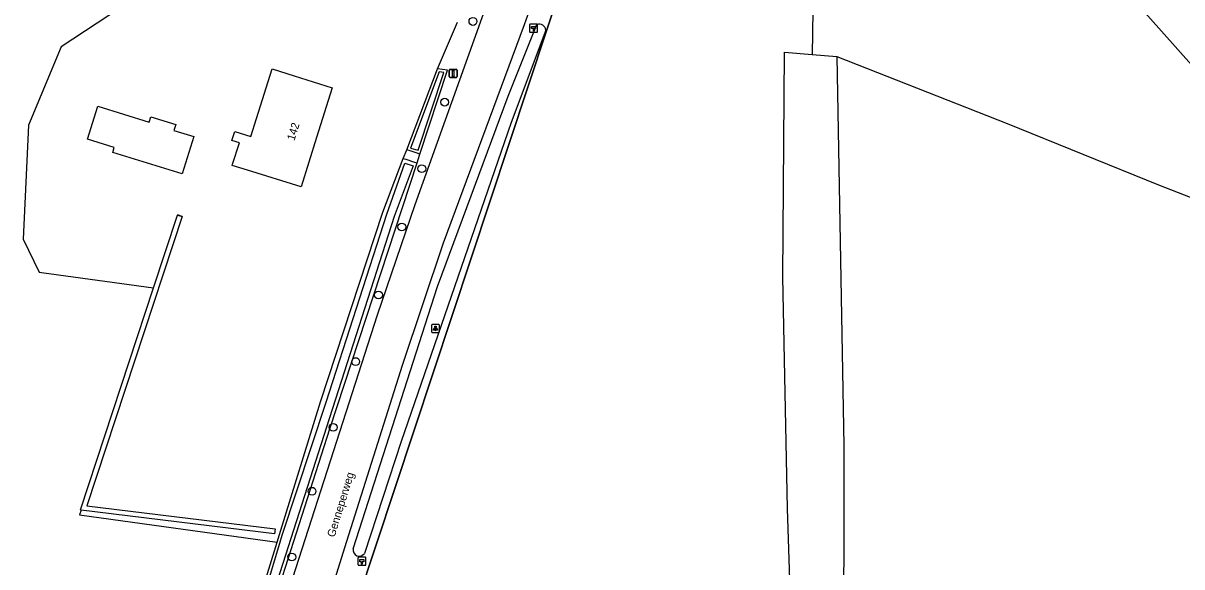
# Model space of a CAD drawing. Extents: x 160203 to 161526, y 379529 to 381797.
# Drawn here: x 160911.8 to 161056.6, y 381132.5 to 381200.5 of the extents above; entities that cross this region are included whole.
import ezdxf

# ---------------------------------------------------------------- set-up
doc = ezdxf.new("R2010")
doc.units = 0
for name, color, linetype in [('IMGEO_Berm_groen', 7, 'Continuous'), ('IMGEO_Boom', 7, 'Continuous'), ('IMGEO_Bouwland', 7, 'Continuous'), ('IMGEO_Erf', 7, 'Continuous'), ('IMGEO_Grasland_agrarisch', 7, 'Continuous'), ('IMGEO_Groenvoorziening', 7, 'Continuous'), ('IMGEO_Haag', 7, 'Continuous'), ('IMGEO_Hectometerpaal', 7, 'Continuous'), ('IMGEO_Hek', 7, 'Continuous'), ('IMGEO_Houtwal', 7, 'Continuous'), ('IMGEO_Lichtpunt', 7, 'Continuous'), ('IMGEO_Loofbos', 7, 'Continuous'), ('IMGEO_Openbare_ruimte_label', 7, 'Continuous'), ('IMGEO_Pand', 7, 'Continuous'), ('IMGEO_Pand_nummerreeks', 7, 'Continuous'), ('IMGEO_Rijbaan_lokaal_gesloten', 7, 'Continuous'), ('IMGEO_Verkeersbordpaal', 7, 'Continuous'), ('IMGEO_Waterloop', 7, 'Continuous')]:
    doc.layers.add(name, color=color, linetype=linetype)

msp = doc.modelspace()

# ---------------------------------------------------------------- linework, layer by layer
at = {"layer": 'IMGEO_Berm_groen'}
for points in [[(160963.6, 381194.73), (160966.09, 381200.58)], [(160961.4, 381184.09), (160964.85, 381194.6), (160963.6, 381194.73)], [(160961.04, 381182.98), (160961.4, 381184.09)], [(160939.06, 381120.95), (160940.77, 381120.43), (160950.14, 381149.71), (160961.04, 381182.98)]]:
    msp.add_lwpolyline(points, dxfattribs=at)
at = {"layer": 'IMGEO_Boom'}
for centre in [(160968.03, 381200.68), (160964.5, 381190.58), (160961.64, 381182.26), (160959.14, 381174.97), (160956.23, 381166.46), (160953.38, 381158.13), (160950.56, 381149.9), (160947.92, 381141.91), (160945.39, 381133.68)]:
    msp.add_circle(centre, 0.489, dxfattribs=at)
at = {"layer": 'IMGEO_Bouwland'}
for points in [[(161010.97, 381081.3), (161010.95, 381074.65), (161003.55, 381076.23), (161000, 381077.09), (160995.21, 381078.26), (160994.38, 381077.68), (160975.97, 381079.3), (160943.93, 381083.76), (160939.3, 381085.02), (160993.95, 381250), (160994.1, 381250.44), (160995.16, 381250.16), (160995.77, 381250), (161000, 381248.89), (161006.71, 381247.12)], [(161010.51, 381202), (161010.41, 381196.55)], [(161013.52, 381196.31), (161034.78, 381187.91), (161053.72, 381180.26), (161083.68, 381168.57)]]:
    msp.add_lwpolyline(points, dxfattribs=at)
at = {"layer": 'IMGEO_Erf'}
for points in [[(160959.75, 381184.63), (160963.6, 381194.73)], [(160943.56, 381135.52), (160943.86, 381136.52), (160948.98, 381153.08), (160956.78, 381176.82), (160959.33, 381183.53)]]:
    msp.add_lwpolyline(points, dxfattribs=at)
at = {"layer": 'IMGEO_Grasland_agrarisch'}
for points in [[(160965.13, 381205.95), (160950.45, 381206.63), (160940.17, 381205.98), (160925.58, 381203.46), (160916.58, 381197.51), (160912.48, 381187.72), (160911.82, 381173.43), (160913.8, 381169.33), (160914.13, 381169.27), (160928.12, 381167.36)], [(160919.06, 381139.56), (160918.86, 381138.97), (160943.56, 381135.52)], [(160939.06, 381120.95), (160943.56, 381135.52)]]:
    msp.add_lwpolyline(points, dxfattribs=at)
at = {"layer": 'IMGEO_Groenvoorziening'}
for points in [[(160959.33, 381183.53), (160959.75, 381184.63)], [(160961.4, 381184.09), (160961.08, 381184.2), (160960.08, 381184.52), (160959.75, 381184.63)], [(160959.33, 381183.53), (160959.66, 381183.43), (160960.71, 381183.08), (160961.04, 381182.98)], [(160931.1, 381176.45), (160931.68, 381176.29)]]:
    msp.add_lwpolyline(points, dxfattribs=at)
at = {"layer": 'IMGEO_Haag'}
for points in [[(160931.68, 381176.29), (160919.77, 381140.08), (160943.31, 381137.19), (160943.24, 381136.59), (160919.06, 381139.56)], [(160928.12, 381167.36), (160931.1, 381176.45)], [(160931.68, 381176.29), (160931.12, 381176.48), (160931.1, 381176.45)], [(160919.06, 381139.56), (160918.98, 381139.57), (160928.12, 381167.36)]]:
    msp.add_lwpolyline(points, dxfattribs=at)
at = {"layer": 'IMGEO_Hectometerpaal'}
for p, q in [((160975.12, 381200.25), (160975.12, 381199.41)), ((160975.12, 381200.25), (160975.12, 381199.41)), ((160976.03, 381200.33), (160975.19, 381200.33)), ((160976.03, 381200.33), (160975.19, 381200.33)), ((160975.2, 381199.33), (160976.04, 381199.33)), ((160975.2, 381199.33), (160976.04, 381199.33)), ((160976.11, 381199.42), (160976.11, 381200.26)), ((160976.11, 381199.42), (160976.11, 381200.26)), ((160953.66, 381133.56), (160953.66, 381132.72)), ((160953.66, 381133.56), (160953.66, 381132.72)), ((160954.57, 381133.65), (160953.73, 381133.65)), ((160954.57, 381133.65), (160953.73, 381133.65)), ((160953.74, 381132.65), (160954.58, 381132.65)), ((160953.74, 381132.65), (160954.58, 381132.65)), ((160954.66, 381132.73), (160954.66, 381133.57)), ((160954.66, 381132.73), (160954.66, 381133.57))]:
    msp.add_line(p, q, dxfattribs=at)
for points in [[(160975.64, 381199.48), (160975.58, 381199.48), (160975.58, 381199.78), (160975.36, 381199.78), (160975.36, 381200.05), (160975.86, 381200.05), (160975.86, 381199.78), (160975.64, 381199.78), (160975.64, 381199.48)], [(160954.18, 381132.79), (160954.12, 381132.79), (160954.12, 381133.1), (160953.9, 381133.1), (160953.9, 381133.37), (160954.4, 381133.37), (160954.4, 381133.1), (160954.18, 381133.1), (160954.18, 381132.79)]]:
    msp.add_lwpolyline(points, dxfattribs=at)
for centre, start, end in [((160975.19, 381200.25), 92.4484, 184.2845), ((160975.19, 381200.25), 92.4484, 184.2845), ((160975.19, 381199.41), 182.4484, 274.2845), ((160975.19, 381199.41), 182.4484, 274.2845), ((160976.04, 381200.25), 2.4484, 94.2845), ((160976.04, 381200.25), 2.4484, 94.2845), ((160976.04, 381199.41), 272.4484, 4.2845), ((160976.04, 381199.41), 272.4484, 4.2845), ((160953.74, 381133.57), 92.4484, 184.2845), ((160953.74, 381133.57), 92.4484, 184.2845), ((160953.74, 381132.73), 182.4484, 274.2845), ((160953.74, 381132.73), 182.4484, 274.2845), ((160954.58, 381133.57), 2.4484, 94.2845), ((160954.58, 381133.57), 2.4484, 94.2845), ((160954.58, 381132.73), 272.4484, 4.2845), ((160954.58, 381132.73), 272.4484, 4.2845)]:
    msp.add_arc(centre, 0.0779, start, end, dxfattribs=at)
at = {"layer": 'IMGEO_Hek'}
msp.add_lwpolyline([(160995.16, 381250.16), (160994.1, 381250.44), (160993.95, 381250), (160939.3, 381085.02), (160943.93, 381083.76), (160975.97, 381079.3), (160994.38, 381077.68), (160995.21, 381078.26), (161000, 381077.09), (161003.55, 381076.23), (161010.95, 381074.65)], dxfattribs=at)
at = {"layer": 'IMGEO_Houtwal'}
for points in [[(161010.97, 381081.3), (161009.28, 381081.26), (161007.34, 381139.77), (161006.78, 381168.69), (161006.96, 381196.82), (161010.41, 381196.55)], [(161010.41, 381196.55), (161013.52, 381196.31)], [(161013.52, 381196.31), (161014.4, 381147.63), (161014.3, 381086.66), (161013.49, 381081.36)]]:
    msp.add_lwpolyline(points, dxfattribs=at)
at = {"layer": 'IMGEO_Lichtpunt'}
for p, q in [((160962.85, 381162.67), (160962.85, 381161.87)), ((160962.85, 381162.67), (160962.85, 381161.87)), ((160963.75, 381162.77), (160962.94, 381162.77)), ((160963.75, 381162.77), (160962.94, 381162.77)), ((160962.94, 381161.77), (160963.75, 381161.77)), ((160962.94, 381161.77), (160963.75, 381161.77)), ((160963.85, 381161.87), (160963.85, 381162.67)), ((160963.85, 381161.87), (160963.85, 381162.67))]:
    msp.add_line(p, q, dxfattribs=at)
for points in [[(160963.22, 381162.34), (160963.26, 381162.31), (160963.08, 381162.05), (160963.04, 381162.08), (160963.22, 381162.34)], [(160963.33, 381162.29), (160963.37, 381162.29), (160963.37, 381161.97), (160963.33, 381161.97), (160963.33, 381162.29)], [(160963.44, 381162.31), (160963.47, 381162.34), (160963.66, 381162.07), (160963.62, 381162.05), (160963.44, 381162.31)]]:
    msp.add_lwpolyline(points, dxfattribs=at)
msp.add_circle((160963.35, 381162.47), 0.0994, dxfattribs=at)
for centre, start, end in [((160962.94, 381162.67), 90, 180), ((160962.94, 381162.67), 90, 180), ((160962.94, 381161.87), 180, 270), ((160962.94, 381161.87), 180, 270), ((160963.75, 381162.67), 0, 90), ((160963.75, 381162.67), 0, 90), ((160963.75, 381161.87), 270, 0), ((160963.75, 381161.87), 270, 360)]:
    msp.add_arc(centre, 0.0946, start, end, dxfattribs=at)
at = {"layer": 'IMGEO_Loofbos'}
msp.add_lwpolyline([(161082.58, 381175.75), (161077.67, 381178.3), (161070.58, 381182.79), (161061.58, 381191.03), (161050.68, 381203.28), (161037.87, 381219.57), (161034.13, 381223.39), (161013.62, 381201.68), (161010.51, 381202)], dxfattribs=at)
at = {"layer": 'IMGEO_Pand'}
for points in [[(160939.84, 381182.08), (160937.95, 381182.67), (160938, 381182.82), (160938.84, 381185.5), (160937.91, 381185.79), (160938.26, 381186.9), (160940.27, 381186.27), (160940.98, 381188.54), (160942.93, 381194.74), (160945.68, 381193.87), (160950.45, 381192.38), (160948.5, 381186.17), (160946.55, 381179.97), (160939.84, 381182.08)], [(160931.68, 381181.6), (160923.03, 381184.29), (160923.2, 381184.91), (160919.87, 381185.95), (160921.16, 381190.08), (160927.57, 381188.08), (160927.78, 381188.74), (160930.88, 381187.77), (160930.66, 381187.05), (160933.14, 381186.28), (160931.68, 381181.6)]]:
    msp.add_lwpolyline(points, dxfattribs=at)
at = {"layer": 'IMGEO_Rijbaan_lokaal_gesloten'}
for points in [[(160986.23, 381250.71), (160986.06, 381250), (160984.88, 381245.18), (160960.77, 381177.72), (160956.05, 381163.95), (160940.76, 381116.4)], [(160915.33, 381026.22), (160921.46, 381041.16), (160927.74, 381060.12), (160928.46, 381062.22), (160929.84, 381066.2), (160933.95, 381078.05), (160934.49, 381079.74), (160949.77, 381127.68), (160952.02, 381134.89), (160959.23, 381157.7), (160964.36, 381173), (160974.47, 381200.28), (160974.68, 381200.87), (160988.22, 381238.39), (160991.59, 381248.5)]]:
    msp.add_lwpolyline(points, dxfattribs=at)
at = {"layer": 'IMGEO_Verkeersbordpaal'}
for p, q in [((160965.07, 381193.78), (160965.07, 381194.58)), ((160965.07, 381194.58), (160965.07, 381193.78)), ((160965.17, 381194.68), (160965.96, 381194.68)), ((160965.96, 381194.68), (160965.17, 381194.68)), ((160965.96, 381193.68), (160965.17, 381193.68)), ((160965.17, 381193.68), (160965.96, 381193.68)), ((160966.06, 381194.58), (160966.06, 381193.78)), ((160966.06, 381193.78), (160966.06, 381194.58))]:
    msp.add_line(p, q, dxfattribs=at)
msp.add_lwpolyline([(160965.49, 381194.55), (160965.64, 381194.55), (160965.64, 381193.8), (160965.49, 381193.8), (160965.49, 381194.55)], dxfattribs=at)
for centre, start, end in [((160965.17, 381194.58), 90, 180), ((160965.17, 381194.58), 90, 180), ((160965.17, 381193.78), 180, 270), ((160965.17, 381193.78), 180, 270), ((160965.96, 381194.58), 0, 90), ((160965.96, 381194.58), 360, 90), ((160965.96, 381193.78), 270, 0), ((160965.96, 381193.78), 270, 0)]:
    msp.add_arc(centre, 0.1, start, end, dxfattribs=at)
at = {"layer": 'IMGEO_Waterloop'}
for points in [[(160953.05, 381134.71), (160963.59, 381167.51), (160972.42, 381191.32), (160976.03, 381200.31)], [(160977.15, 381199.6), (160972.82, 381188.05), (160959.08, 381148.14)], [(160960.23, 381184.83), (160961.2, 381184.56), (160964.39, 381194.3), (160963.82, 381194.36), (160960.23, 381184.83)], [(160939.64, 381121.3), (160943.88, 381135.42), (160944.19, 381136.41), (160949.68, 381153.06), (160957.28, 381176.57), (160959.5, 381182.97), (160960.55, 381182.63), (160958.17, 381176.29), (160949.71, 381149.93), (160940.49, 381121.04), (160939.64, 381121.3)], [(160959.08, 381148.14), (160954.48, 381134.13)]]:
    msp.add_lwpolyline(points, dxfattribs=at)
for centre, radius, start, end in [((160976.3, 381199.5), 0.852, 6.5141, 108.5302), ((160953.83, 381134.58), 0.788, 170.441, 324.9041)]:
    msp.add_arc(centre, radius, start, end, dxfattribs=at)

# ---------------------------------------------------------------- texts
at = {"layer": 'IMGEO_Openbare_ruimte_label'}
msp.add_text('Genneperweg', height=1, rotation=72.9605, dxfattribs=at).set_placement((160950.73, 381136.08))
at = {"layer": 'IMGEO_Pand_nummerreeks'}
msp.add_text('142', height=1, rotation=72.5594, dxfattribs=at).set_placement((160945.71, 381185.7))

doc.saveas('drawing.dxf')
